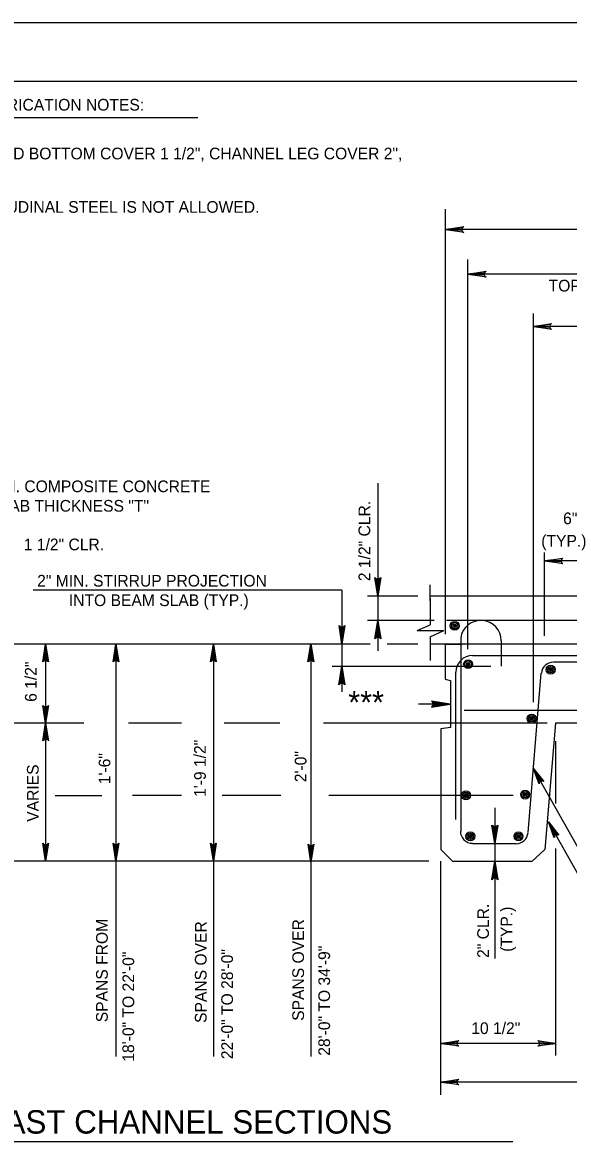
# Model space of a CAD drawing. Extents: x 642009 to 642864, y 298232 to 300014.
# Drawn here: x 642283.1 to 642423.1, y 299723.7 to 300013.8 of the extents above; entities that cross this region are included whole.
import ezdxf

# ---------------------------------------------------------------- set-up
doc = ezdxf.new("R2010")
doc.units = 0
for name, color, linetype in [('1', 7, 'Continuous'), ('2', 7, 'Continuous'), ('PLT-BNDY', 7, 'Continuous')]:
    doc.layers.add(name, color=color, linetype=linetype)

msp = doc.modelspace()

# ---------------------------------------------------------------- linework, layer by layer
at = {"layer": '1'}
for points in [[(642396.06, 299960.17), (642395.89, 299960.5), (642391.52, 299960.74), (642396.06, 299960.17), (642396.3, 299959.97), (642391.52, 299960.74), (642395.89, 299960.96), (642396.05, 299961.28), (642391.52, 299960.74), (642396.3, 299961.5), (642396.05, 299961.28)], [(642401.76, 299948.73), (642401.6, 299949.06), (642397.22, 299949.3), (642401.76, 299948.73), (642402, 299948.53), (642397.22, 299949.3), (642401.59, 299949.52), (642401.75, 299949.84), (642397.22, 299949.3), (642402, 299950.06), (642401.75, 299949.84)], [(642418.56, 299935.27), (642418.39, 299935.6), (642414.02, 299935.84), (642418.56, 299935.27), (642418.8, 299935.07), (642414.02, 299935.84), (642418.39, 299936.05), (642418.55, 299936.38), (642414.02, 299935.84), (642418.8, 299936.6), (642418.55, 299936.38)], [(642421.48, 299875.14), (642421.31, 299875.47), (642416.94, 299875.71), (642421.48, 299875.14), (642421.71, 299874.94), (642416.94, 299875.71), (642421.31, 299875.93), (642421.47, 299876.25), (642416.94, 299875.71), (642421.71, 299876.47), (642421.47, 299876.25)], [(642374.8, 299871.26), (642374.47, 299871.09), (642374.23, 299866.72), (642374.8, 299871.26), (642375, 299871.49), (642374.23, 299866.72), (642374.01, 299871.08), (642373.68, 299871.24), (642374.23, 299866.72), (642373.47, 299871.49), (642373.68, 299871.24)], [(642373.66, 299855.94), (642373.98, 299856.11), (642374.23, 299860.48), (642373.66, 299855.94), (642373.46, 299855.71), (642374.23, 299860.48), (642374.44, 299856.11), (642374.77, 299855.95), (642374.23, 299860.48), (642374.98, 299855.71), (642374.77, 299855.95)], [(642365.59, 299858.93), (642365.26, 299858.76), (642365.02, 299854.39), (642365.59, 299858.93), (642365.79, 299859.16), (642365.02, 299854.39), (642364.81, 299858.76), (642364.48, 299858.91), (642365.02, 299854.39), (642364.26, 299859.16), (642364.48, 299858.91)], [(642364.45, 299844.18), (642364.78, 299844.35), (642365.02, 299848.72), (642364.45, 299844.18), (642364.25, 299843.95), (642365.02, 299848.72), (642365.24, 299844.35), (642365.56, 299844.19), (642365.02, 299848.72), (642365.78, 299843.95), (642365.56, 299844.19)], [(642388.19, 299838.44), (642388.36, 299838.77), (642392.73, 299839.01), (642388.19, 299838.44), (642387.95, 299838.24), (642392.73, 299839.01), (642388.36, 299839.23), (642388.2, 299839.55), (642392.73, 299839.01), (642387.95, 299839.77), (642388.2, 299839.55)], [(642404.79, 299807.74), (642404.46, 299807.57), (642404.22, 299803.2), (642404.79, 299807.74), (642404.99, 299807.97), (642404.22, 299803.2), (642404, 299807.57), (642403.68, 299807.73), (642404.22, 299803.2), (642403.46, 299807.97), (642403.68, 299807.73)], [(642403.65, 299794.16), (642403.98, 299794.33), (642404.22, 299798.7), (642403.65, 299794.16), (642403.45, 299793.93), (642404.22, 299798.7), (642404.44, 299794.33), (642404.76, 299794.17), (642404.22, 299798.7), (642404.98, 299793.93), (642404.76, 299794.17)]]:
    msp.add_lwpolyline(points, dxfattribs=at)
at = {"layer": '2'}
for p, q in [((642048.66, 299998.82), (642834.66, 299998.82)), ((642238.15, 299989.48), (642328.03, 299989.48)), ((642391.52, 299965.98), (642391.52, 299856.89)), ((642500.65, 299960.74), (642391.52, 299960.74)), ((642397.22, 299953.06), (642397.22, 299853.06)), ((642494.46, 299949.3), (642397.22, 299949.3)), ((642414.02, 299939.21), (642414.02, 299839.47)), ((642478.15, 299935.84), (642414.02, 299935.84)), ((642414.02, 299899.55), (642414.02, 299894.48)), ((642374.23, 299895.71), (642374.23, 299852.65)), ((642416.94, 299856.47), (642416.94, 299877.85)), ((642430.88, 299875.71), (642416.94, 299875.71)), ((642387.65, 299865.51), (642387.65, 299869.62)), ((642365.02, 299868.2), (642285.84, 299868.2)), ((642365.02, 299868.2), (642365.02, 299842.17)), ((642384.51, 299866.72), (642371.53, 299866.72)), ((642374.23, 299866.72), (642374.23, 299866.72)), ((642502.67, 299866.72), (642387.65, 299866.72)), ((642387.65, 299866.1), (642387.65, 299859.29)), ((642388.66, 299860.48), (642371.53, 299860.48)), ((642501.93, 299860.48), (642391.81, 299860.48)), ((642384.27, 299857.89), (642387.65, 299859.29)), ((642384.27, 299857.89), (642391.15, 299857.89)), ((642387.65, 299856.22), (642391.15, 299857.89)), ((642387.65, 299856.22), (642387.65, 299850.19)), ((642395.48, 299855.99), (642395.48, 299806.37)), ((642405.87, 299855.23), (642405.87, 299848.72)), ((642372.27, 299854.39), (642271.33, 299854.39)), ((642289, 299854.39), (642289, 299834.14)), ((642307.03, 299854.39), (642307.03, 299798.7)), ((642332.03, 299854.39), (642332.03, 299798.7)), ((642357.03, 299854.39), (642357.03, 299798.7)), ((642384.51, 299854.39), (642376.62, 299854.39)), ((642502.67, 299854.39), (642387.65, 299854.39)), ((642387.65, 299853.47), (642387.65, 299850.71)), ((642391.52, 299854.39), (642395.86, 299854.39)), ((642391.52, 299854.39), (642391.52, 299845.39)), ((642362.53, 299848.72), (642403.18, 299848.72)), ((642493.64, 299851.38), (642398.5, 299851.38)), ((642430.88, 299849.71), (642419.25, 299849.71)), ((642394.16, 299847.21), (642394.16, 299809.39)), ((642416.07, 299846.92), (642412.71, 299806.01)), ((642391.52, 299845.39), (642392.83, 299845.01)), ((642392.83, 299845.01), (642392.83, 299833.01)), ((642392.73, 299839.01), (642384.65, 299839.01)), ((642495.58, 299837.32), (642396.4, 299837.32)), ((642298.81, 299834.14), (642262.8, 299834.14)), ((642289, 299834.14), (642289, 299798.7)), ((642323.83, 299834.14), (642310.28, 299834.14)), ((642349.1, 299834.14), (642334.77, 299834.14)), ((642417.64, 299834.14), (642360.31, 299834.14)), ((642392.83, 299833.01), (642390.4, 299832.64)), ((642390.4, 299832.64), (642390.4, 299801.7)), ((642419.83, 299834.14), (642417.02, 299801.7)), ((642472.33, 299834.14), (642419.83, 299834.14)), ((642419.83, 299829.45), (642419.83, 299813.51)), ((642436.44, 299782.86), (642414.07, 299822.57)), ((642291.48, 299815.57), (642303.39, 299815.57)), ((642323.83, 299815.57), (642311.31, 299815.57)), ((642349.36, 299815.57), (642334.25, 299815.57)), ((642376.96, 299815.57), (642361.61, 299815.57)), ((642408.96, 299815.57), (642376.96, 299815.57)), ((642404.22, 299812.4), (642404.22, 299803.2)), ((642442.37, 299765.44), (642417.96, 299808.76)), ((642398.49, 299803.2), (642409.71, 299803.2)), ((642404.22, 299803.2), (642404.22, 299798.7)), ((642390.4, 299801.7), (642393.4, 299798.7)), ((642417.02, 299801.7), (642413.65, 299798.51)), ((642419.83, 299801.96), (642419.83, 299748.83)), ((642387.3, 299798.7), (642240.26, 299798.7)), ((642307.03, 299798.7), (642307.03, 299748.61)), ((642332.03, 299798.7), (642332.03, 299748.61)), ((642357.03, 299798.7), (642357.03, 299748.61)), ((642390.4, 299738.72), (642390.4, 299798.7)), ((642393.4, 299798.7), (642413.65, 299798.7)), ((642404.22, 299798.7), (642404.22, 299773.76)), ((642419.83, 299751.95), (642390.4, 299751.95)), ((642501.77, 299742.02), (642390.4, 299742.02)), ((642221.12, 299726.76), (642408.84, 299726.76))]:
    msp.add_line(p, q, dxfattribs=at)
for points in [[(642288.46, 299850.03), (642288.77, 299850.19), (642289, 299854.39), (642288.46, 299850.03), (642288.26, 299849.8), (642289, 299854.39), (642289.21, 299850.19), (642289.52, 299850.04), (642289, 299854.39), (642289.73, 299849.8), (642289.52, 299850.04)], [(642306.48, 299850.03), (642306.8, 299850.19), (642307.03, 299854.39), (642306.48, 299850.03), (642306.29, 299849.8), (642307.03, 299854.39), (642307.24, 299850.19), (642307.55, 299850.04), (642307.03, 299854.39), (642307.76, 299849.8), (642307.55, 299850.04)], [(642331.48, 299850.03), (642331.8, 299850.19), (642332.03, 299854.39), (642331.48, 299850.03), (642331.29, 299849.8), (642332.03, 299854.39), (642332.24, 299850.19), (642332.55, 299850.04), (642332.03, 299854.39), (642332.76, 299849.8), (642332.55, 299850.04)], [(642356.48, 299850.03), (642356.8, 299850.19), (642357.03, 299854.39), (642356.48, 299850.03), (642356.29, 299849.8), (642357.03, 299854.39), (642357.24, 299850.19), (642357.55, 299850.04), (642357.03, 299854.39), (642357.76, 299849.8), (642357.55, 299850.04)], [(642289.54, 299838.44), (642289.23, 299838.28), (642288.99, 299834.08), (642289.54, 299838.44), (642289.73, 299838.66), (642288.99, 299834.08), (642288.79, 299838.28), (642288.47, 299838.43), (642288.99, 299834.08), (642288.27, 299838.66), (642288.47, 299838.43)], [(642288.46, 299829.78), (642288.77, 299829.95), (642289, 299834.14), (642288.46, 299829.78), (642288.26, 299829.56), (642289, 299834.14), (642289.21, 299829.95), (642289.52, 299829.8), (642289, 299834.14), (642289.73, 299829.56)], [(642415.62, 299818.77), (642415.8, 299819.05), (642414.07, 299822.57), (642415.62, 299818.77), (642415.57, 299818.5), (642414.07, 299822.57), (642416.16, 299819.25), (642416.48, 299819.27), (642414.07, 299822.57), (642416.76, 299819.17), (642416.48, 299819.27)], [(642419.51, 299804.96), (642419.7, 299805.24), (642417.96, 299808.76), (642419.51, 299804.96), (642419.46, 299804.69), (642417.96, 299808.76), (642420.05, 299805.44), (642420.38, 299805.46), (642417.96, 299808.76), (642420.65, 299805.37), (642420.38, 299805.46)], [(642289.55, 299803.06), (642289.24, 299802.9), (642289, 299798.7), (642289.55, 299803.06), (642289.74, 299803.28), (642289, 299798.7), (642288.8, 299802.89), (642288.48, 299803.05), (642289, 299798.7), (642288.28, 299803.28), (642288.48, 299803.05)], [(642307.58, 299803.06), (642307.26, 299802.9), (642307.03, 299798.7), (642307.58, 299803.06), (642307.77, 299803.28), (642307.03, 299798.7), (642306.82, 299802.89), (642306.51, 299803.05), (642307.03, 299798.7), (642306.3, 299803.28), (642306.51, 299803.05)], [(642332.58, 299803.06), (642332.26, 299802.9), (642332.03, 299798.7), (642332.58, 299803.06), (642332.77, 299803.28), (642332.03, 299798.7), (642331.82, 299802.89), (642331.51, 299803.05), (642332.03, 299798.7), (642331.3, 299803.28), (642331.51, 299803.05)], [(642357.61, 299802.83), (642357.3, 299802.67), (642357.07, 299798.47), (642357.61, 299802.83), (642357.81, 299803.06), (642357.07, 299798.47), (642356.86, 299802.67), (642356.55, 299802.82), (642357.07, 299798.47), (642356.34, 299803.06), (642356.55, 299802.82)], [(642394.76, 299751.41), (642394.59, 299751.72), (642390.4, 299751.95), (642394.76, 299751.41), (642394.98, 299751.21), (642390.4, 299751.95), (642394.59, 299752.16), (642394.74, 299752.47), (642390.4, 299751.95), (642394.98, 299752.68), (642394.74, 299752.47)], [(642415.47, 299752.5), (642415.64, 299752.18), (642419.83, 299751.95), (642415.47, 299752.5), (642415.25, 299752.69), (642419.83, 299751.95), (642415.64, 299751.75), (642415.49, 299751.43), (642419.83, 299751.95), (642415.25, 299751.22), (642415.49, 299751.43)], [(642394.76, 299741.48), (642394.59, 299741.79), (642390.4, 299742.02), (642394.76, 299741.48), (642394.98, 299741.29), (642390.4, 299742.02), (642394.59, 299742.23), (642394.74, 299742.54), (642390.4, 299742.02), (642394.98, 299742.75), (642394.74, 299742.54)]]:
    msp.add_lwpolyline(points, dxfattribs=at)
for centre, radius in [((642393.92, 299859.08), 1.14), ((642393.92, 299859.08), 0.817), ((642393.92, 299859.08), 0.447), ((642393.92, 299859.08), 0.225), ((642393.92, 299859.08), 0.0966), ((642397.37, 299849.24), 1.14), ((642397.37, 299849.24), 0.817), ((642397.37, 299849.24), 0.447), ((642397.37, 299849.24), 0.225), ((642397.37, 299849.24), 0.0966), ((642418.54, 299847.84), 1.14), ((642418.54, 299847.84), 0.817), ((642418.54, 299847.84), 0.447), ((642418.54, 299847.84), 0.225), ((642418.54, 299847.84), 0.0966), ((642413.68, 299835.27), 1.14), ((642413.68, 299835.27), 0.817), ((642413.68, 299835.27), 0.447), ((642413.68, 299835.27), 0.225), ((642413.68, 299835.27), 0.0966), ((642412, 299815.77), 1.14), ((642396.83, 299815.58), 1.14), ((642396.83, 299815.58), 0.817), ((642396.83, 299815.58), 0.447), ((642396.83, 299815.58), 0.225), ((642396.83, 299815.58), 0.0966), ((642412, 299815.77), 0.817), ((642412, 299815.77), 0.447), ((642412, 299815.77), 0.225), ((642412, 299815.77), 0.0966), ((642397.95, 299805.08), 1.14), ((642397.95, 299805.08), 0.817), ((642397.95, 299805.08), 0.447), ((642397.95, 299805.08), 0.225), ((642397.95, 299805.08), 0.0966), ((642410.31, 299805.08), 1.14), ((642410.31, 299805.08), 0.817), ((642410.31, 299805.08), 0.447), ((642410.31, 299805.08), 0.225), ((642410.31, 299805.08), 0.0966)]:
    msp.add_circle(centre, radius, dxfattribs=at)
for centre, radius, start, end in [((642400.65, 299855.23), 5.23, 0, 171.6217), ((642398.5, 299847.21), 4.25, 90, 180), ((642419.24, 299846.66), 3.09, 90, 175.2381), ((642398.49, 299806.37), 3.09, 180, 270), ((642409.67, 299806.25), 3.09, 270, 355.2392)]:
    msp.add_arc(centre, radius, start, end, dxfattribs=at)
at = {"layer": 'PLT-BNDY'}
msp.add_lwpolyline([(642008.66, 300013.82), (642849.66, 300013.82), (642849.66, 299419.82), (642008.66, 299419.82)], close=True, dxfattribs=at)

# ---------------------------------------------------------------- texts
at = {"layer": '2'}
for s, height, p in [('CHANNEL BEAM FABRICATION NOTES:', 3, (642238.49, 299991.25)), ('BEAM SLAB TOP AND BOTTOM COVER 1 1/2", CHANNEL LEG COVER 2",', 3, (642241.89, 299978.74)), ('2. SPLICING OF LONGITUDINAL STEEL IS NOT ALLOWED.', 3, (642233.05, 299965.03)), ('TOP SLAB OF BEAM', 3, (642418.03, 299944.84)), ('5 1/2" MIN. COMPOSITE CONCRETE', 3, (642262.51, 299893.36)), ('DECK SLAB THICKNESS "T"', 3, (642262.51, 299888.36)), ('6"', 3, (642421.74, 299885.14)), ('(TYP.)', 3, (642416.14, 299879.38)), ('2" MIN. STIRRUP PROJECTION', 3, (642286.82, 299869.14)), ('INTO BEAM SLAB (TYP.)', 3, (642294.96, 299864.14)), ('***', 5.88, (642366.62, 299836.5)), ('10 1/2"', 3, (642398.18, 299754.35)), ('TYPICAL PRECAST CHANNEL SECTIONS', 6, (642220.53, 299728.81))]:
    msp.add_text(s, height=height, dxfattribs=at).set_placement(p)
for s, rotation, p in [('2 1/2" CLR.', 90, (642372.26, 299870.53)), ('1 1/2" CLR.', 360, (642283.4, 299878.45)), ('6 1/2"', 90, (642286.7, 299839.57)), ('1\'-9 1/2"', 90, (642330.09, 299815.16)), ('1\'-6"', 90, (642305.6, 299818.43)), ('2\'-0"', 90, (642355.9, 299818.95)), ('VARIES', 90, (642287.21, 299808.8)), ('2" CLR.', 90, (642402.72, 299773.87)), ('(TYP.)', 90, (642408.72, 299775.44)), ('SPANS FROM ', 90, (642304.94, 299757.37)), ('SPANS OVER', 90, (642330.29, 299757.2)), ('SPANS OVER', 90, (642355.28, 299757.74)), ('28\'-0" TO 34\'-9"', 90, (642361.96, 299748.77)), ('18\'-0" TO 22\'-0"', 90, (642311.71, 299747.25)), ('22\'-0" TO 28\'-0"', 90, (642337.06, 299747.9))]:
    msp.add_text(s, height=3, rotation=rotation, dxfattribs=at).set_placement(p)

doc.saveas('drawing.dxf')
